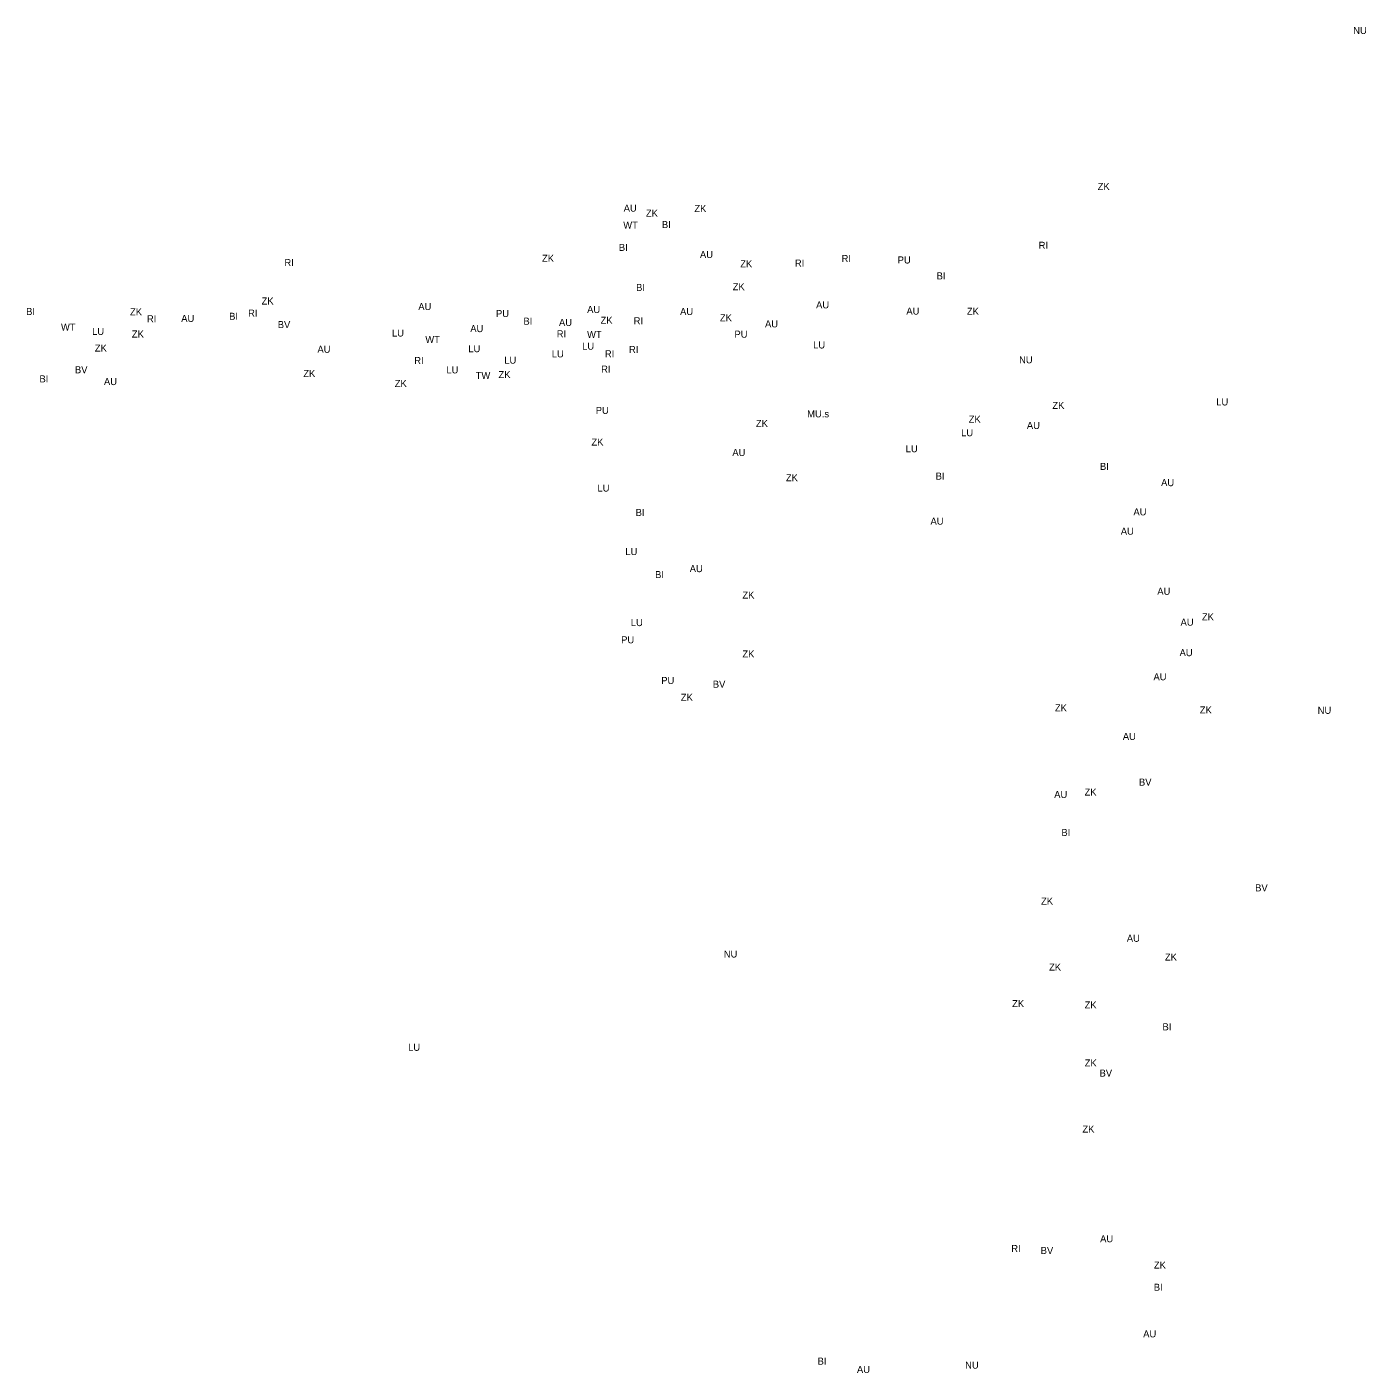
# Model space of a CAD drawing. Extents: x -439151 to -433911, y -1129946 to -1121460.
# Drawn here: x -436520 to -434613, y -1125700 to -1123784 of the extents above; entities that cross this region are included whole.
import ezdxf

# ---------------------------------------------------------------- set-up
doc = ezdxf.new("R2010")
doc.units = 0
doc.layers.add('POPIS PRESTAVBA', color=7, linetype='Continuous')
doc.layers.add('ZASTAVITELNA PLOCHA', color=7, linetype='Continuous')

msp = doc.modelspace()

# ---------------------------------------------------------------- texts
at = {"layer": 'POPIS PRESTAVBA'}
for s, p in [('NU', (-434631.7, -1123793.9)), ('ZK', (-434995.5, -1124016)), ('AU', (-435670.3, -1124046.8)), ('ZK', (-435638.7, -1124054)), ('ZK', (-435569.7, -1124047.4)), ('WT', (-435670.9, -1124070.9)), ('BI', (-435615.9, -1124070.2)), ('RI', (-435079.5, -1124099.7)), ('ZK', (-435786.6, -1124118.2)), ('BI', (-435677.2, -1124102.7)), ('AU', (-435561.7, -1124112.9)), ('RI', (-435360.1, -1124118.6)), ('RI', (-436153.3, -1124124.3)), ('ZK', (-435504.4, -1124126.1)), ('RI', (-435426.6, -1124125)), ('PU', (-435280.2, -1124120.6)), ('BI', (-435224.7, -1124143.3)), ('BI', (-435652.6, -1124159.7)), ('ZK', (-435515.1, -1124158.7)), ('BI', (-436521, -1124193.9)), ('ZK', (-436373.1, -1124194.4)), ('RI', (-436205, -1124196.2)), ('ZK', (-436185.8, -1124179)), ('AU', (-435962.7, -1124186.9)), ('AU', (-435722.3, -1124191.1)), ('AU', (-435590, -1124194)), ('AU', (-435396.4, -1124184.5)), ('AU', (-435267.9, -1124193.4)), ('ZK', (-435181.7, -1124193.6)), ('RI', (-436349, -1124204.3)), ('AU', (-436300.2, -1124203.8)), ('BI', (-436232, -1124200.8)), ('BV', (-436162.8, -1124212.6)), ('PU', (-435852.1, -1124196.9)), ('BI', (-435813, -1124207.8)), ('AU', (-435762.4, -1124209.6)), ('ZK', (-435703.2, -1124206.4)), ('RI', (-435656.1, -1124207.2)), ('ZK', (-435533.3, -1124202.9)), ('AU', (-435469.1, -1124211.6)), ('WT', (-436471.4, -1124216.1)), ('LU', (-436427.1, -1124222.3)), ('ZK', (-436370.5, -1124226)), ('LU', (-436000.2, -1124224.6)), ('WT', (-435952.7, -1124233.7)), ('AU', (-435888.7, -1124218.3)), ('RI', (-435765.6, -1124225.8)), ('WT', (-435722.4, -1124226.7)), ('PU', (-435512.6, -1124226.3)), ('ZK', (-436423.2, -1124246)), ('AU', (-436106.3, -1124247.7)), ('LU', (-435891.5, -1124246.9)), ('LU', (-435729.5, -1124243.3)), ('RI', (-435697.1, -1124254.1)), ('RI', (-435662.7, -1124248.1)), ('LU', (-435400.6, -1124241.6)), ('RI', (-435968.5, -1124263.8)), ('LU', (-435840.3, -1124263.2)), ('LU', (-435772.7, -1124254.3)), ('NU', (-435107.4, -1124262.7)), ('BI', (-436502, -1124289.9)), ('ZK', (-436126.4, -1124282.2)), ('LU', (-435922.7, -1124277.1)), ('TW', (-435881, -1124285)), ('ZK', (-435848.5, -1124283.8)), ('RI', (-435702.4, -1124276)), ('AU', (-436410.2, -1124293.7)), ('ZK', (-435996.2, -1124296.4)), ('ZK', (-435060, -1124327.6)), ('LU', (-434826.7, -1124322.7)), ('PU', (-435710.1, -1124334.7)), ('MU.s', (-435409.1, -1124339.6)), ('ZK', (-435179.1, -1124347.3)), ('ZK', (-435482.1, -1124353.3)), ('LU', (-435189.9, -1124366.5)), ('AU', (-435096.3, -1124356.1)), ('ZK', (-435716.2, -1124379.8)), ('AU', (-435515.6, -1124394.7)), ('LU', (-435268.8, -1124389.3)), ('BI', (-434992.2, -1124414.4)), ('LU', (-435707.6, -1124445.3)), ('ZK', (-435439.4, -1124430.6)), ('BI', (-435226.1, -1124428.3)), ('AU', (-434905.2, -1124437.6)), ('AU', (-434944.6, -1124479.2)), ('AU', (-435233.5, -1124492.4)), ('AU', (-434962.6, -1124506.7)), ('LU', (-435667.9, -1124535.7)), ('AU', (-435576.3, -1124560)), ('BI', (-435625.6, -1124568.5)), ('ZK', (-435501.3, -1124597.6)), ('AU', (-434910.6, -1124592.2)), ('LU', (-435660.1, -1124636.8)), ('AU', (-434877.5, -1124636.2)), ('ZK', (-434847.1, -1124628.6)), ('PU', (-435673.9, -1124661.3)), ('ZK', (-435501.3, -1124681.4)), ('AU', (-434878.9, -1124679.6)), ('AU', (-434916.1, -1124713.9)), ('PU', (-435616.8, -1124719.2)), ('BV', (-435543.4, -1124724.5)), ('ZK', (-435588.9, -1124743.1)), ('ZK', (-435056.4, -1124758.2)), ('ZK', (-434850.1, -1124761.2)), ('NU', (-434682.3, -1124761.7)), ('AU', (-434959.7, -1124798.8)), ('BV', (-434936.7, -1124863.9)), ('AU', (-435057.4, -1124881.5)), ('ZK', (-435014.2, -1124878.1)), ('BI', (-435047.1, -1124935.5)), ('BV', (-434771.3, -1125014.4)), ('ZK', (-435076.1, -1125033.3)), ('AU', (-434954, -1125086.2)), ('NU', (-435527.8, -1125108.6)), ('ZK', (-434899.8, -1125112.9)), ('ZK', (-435064.7, -1125127.2)), ('ZK', (-435117.3, -1125179.2)), ('ZK', (-435014.1, -1125181.1)), ('BI', (-434903.2, -1125212.2)), ('LU', (-435977.2, -1125241.4)), ('ZK', (-435014, -1125263.7)), ('BV', (-434992.8, -1125278.1)), ('ZK', (-435017.2, -1125357.8)), ('AU', (-434992, -1125513.9)), ('RI', (-435118.5, -1125527.9)), ('BV', (-435076.6, -1125530.6)), ('ZK', (-434915.5, -1125551.4)), ('BI', (-434915.6, -1125583)), ('AU', (-434930.7, -1125649.3)), ('BI', (-435394.2, -1125688.2)), ('AU', (-435338.2, -1125700)), ('NU', (-435184.2, -1125693.8))]:
    msp.add_text(s, height=10, dxfattribs=at).set_placement(p)
at = {"layer": 'ZASTAVITELNA PLOCHA'}
for s, p in [('BV', (-436451.5, -1124276.9)), ('BI', (-435653.2, -1124480))]:
    msp.add_text(s, height=10, dxfattribs=at).set_placement(p)

doc.saveas('drawing.dxf')
